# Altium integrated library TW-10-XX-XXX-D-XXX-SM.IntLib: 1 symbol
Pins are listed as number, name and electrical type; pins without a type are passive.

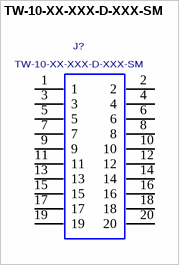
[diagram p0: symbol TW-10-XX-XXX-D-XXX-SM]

## TW-10-XX-XXX-D-XXX-SM
designator J?
HIGH TEMP 2.0MM TERMINAL STRIP,; MANUFACTURER: SAMTEC
footprint TW-10-XX-XXX-D-XXX-SM
pins: 1, 2, 3, 4, 5, 6, 7, 8, 9, 10, 11, 12, 13, 14, 15, 16, 17, 18, 19, 20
